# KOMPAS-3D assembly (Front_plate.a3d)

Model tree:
1. X Axis
2. Y Axis
3. Z Axis
4. Origin
5. Linear Pattern:1  (labels: Instance ( 2, 1 );; Instance ( 3, 1 );; Instance ( 4, 1 );; Instance ( 5, 1 );)
     Included Angle = 90; N 2 = 1; Spacing 2 = 10; Orientation = 1

Expressions: (FP_W-(2*Delta)); (FP_W-(2*Delta))-100
Referenced files in C:\Work\01 К О М П А С\Модели примеры\2009_04_For_Poland_AXAPACK\My sample\Box_sample\: skrzynia1.a3d|L, skrzynia1.a3d|H, skrzynia1.a3d|NR_Front, skrzynia1.a3d|Delta, Front_plate.m3d, rail3.m3d
Referenced files in C:\Work\01 К О М П А С\Модели примеры\2009_04_For_Poland_AXAPACK\My sample\: skrzynia1.a3d
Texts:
  Three Point Plane
  Plane at Angle
  Line and Point Plane
  Axis through Two Vertices
  Axis of Feature
  Axis of Conical Surface
  Axis through Edge
  Trim by Surface
  Trim by Sketch
  Intersection Axis of Two Planes
  Two Line Plane
  Line and Face Plane
  Pattern by Sample
  Point in CM
  Feature with No History
  Linear Dimension from Line to Point
  Surface Finish Symbol
  Geometric Tolerance Symbol
  Leader #1
  Leader #2
  Leader #3
  Shape Deviations and Datum
  Node point number
  Mark of coordination axis
  Node point designation
  Mark/Reference designation with leader
  Mark/reference designation on line
  Mark/Reference designation without leader
  LR2
  Instance ( 2, 1 );
  Instance ( 3, 1 );
  Instance ( 4, 1 );
  Instance ( 5, 1 );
